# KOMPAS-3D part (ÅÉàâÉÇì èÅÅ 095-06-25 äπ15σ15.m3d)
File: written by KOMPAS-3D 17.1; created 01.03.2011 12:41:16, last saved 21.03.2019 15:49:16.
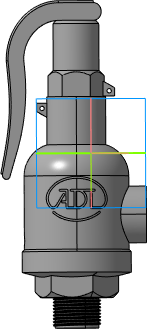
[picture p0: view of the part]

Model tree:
1. Операция без истории:1

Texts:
  Viktor2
